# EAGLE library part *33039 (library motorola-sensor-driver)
Closed Loop Brushless Motor Adapter *NCV33039: Tlow = -40C, Thigh = +125C. Guaranteed by design. http://onsemi.com; mc33039-d.pdf
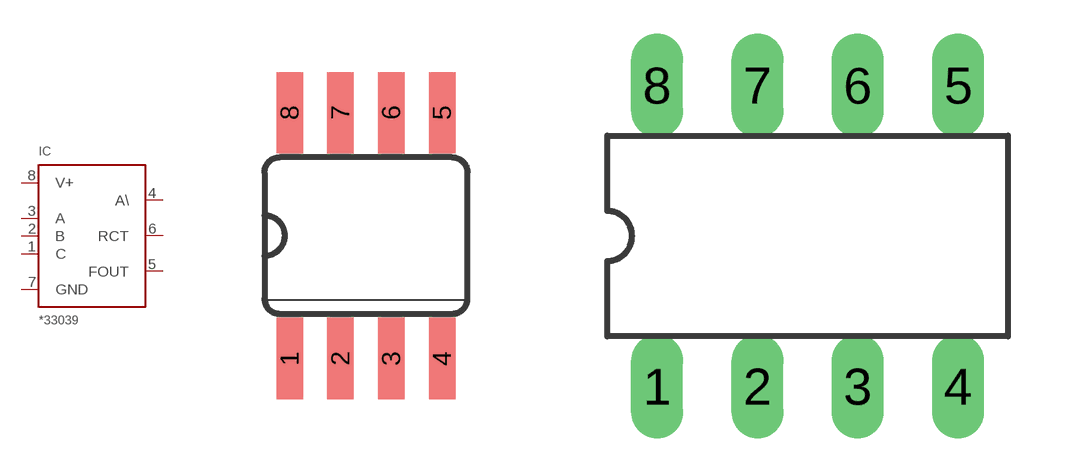
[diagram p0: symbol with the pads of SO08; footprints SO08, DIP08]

Designator prefix IC

## MC33039D, NCV33039D  [SO08]
1  C  in
2  B  in
3  A  in
4  A\  out
5  FOUT  out
6  RCT  pas
7  GND  pwr
8  V+  pwr

## MC33039P  [DIP08]
Pads as for SO08

## Footprint SO08 (pad centres in mm)
Small Outline Package SO-8, CASE 751
smd 0.66 x 2.032: 1 -1.905,-3.073; 2 -0.635,-3.073; 3 0.635,-3.073; 4 1.905,-3.073; 5 1.905,3.073; 6 0.635,3.073; 7 -0.635,3.073; 8 -1.905,3.073

## Footprint DIP08 (pad centres in mm)
Dual In Line
drill 0.813 long: 1 -3.81,-3.81; 2 -1.27,-3.81; 3 1.27,-3.81; 4 3.81,-3.81; 5 3.81,3.81; 6 1.27,3.81; 7 -1.27,3.81; 8 -3.81,3.81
